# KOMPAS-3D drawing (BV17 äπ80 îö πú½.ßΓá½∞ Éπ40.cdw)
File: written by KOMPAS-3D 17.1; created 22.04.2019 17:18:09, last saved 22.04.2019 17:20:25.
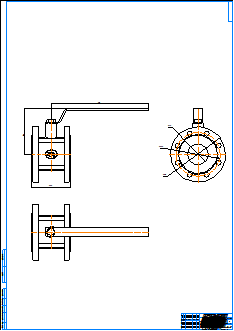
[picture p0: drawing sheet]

Sheet 1: A0, portrait

Title block, sheet 1: name: BV17 Ду80 МФ угл.сталь Ру40; material: Внимание! Данный продукт является объектом авторского права ООО «Торговый Дом АДЛ». / Запрещается изменение, копирование, распространение / (в том числе путем копирования на другие сайты и ресурсы в Интернете) / или любое иное использование информации и объектов без предварительного / согласия правообладателя (ООО «Торговый Дом АДЛ»).; mass: 15,22; sheets: 1; organisation: ООО "Торговый дом АДЛ"; sheet format: A0; stored path: \\adlc.lan\data\АДЛ_ПКД\3D-модели\ADL production\Краны шаровые серии BV\BV17 МФ угл.сталь Ру40\KOMPAS 2D\BV17 Ду80 МФ угл.сталь Ру40.cdw

Views: Вид 1, Проекционный вид 2, Проекционный вид 3
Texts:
  user
Dimensions and other numbers on the sheet: 350; 164; 141; 75; 160; 200; 1:1; 1; 15,22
